// Mitsubishi GX Works2 project: 三菱模版   PLC: FX3U/FX3UC

PROGRAM MAIN
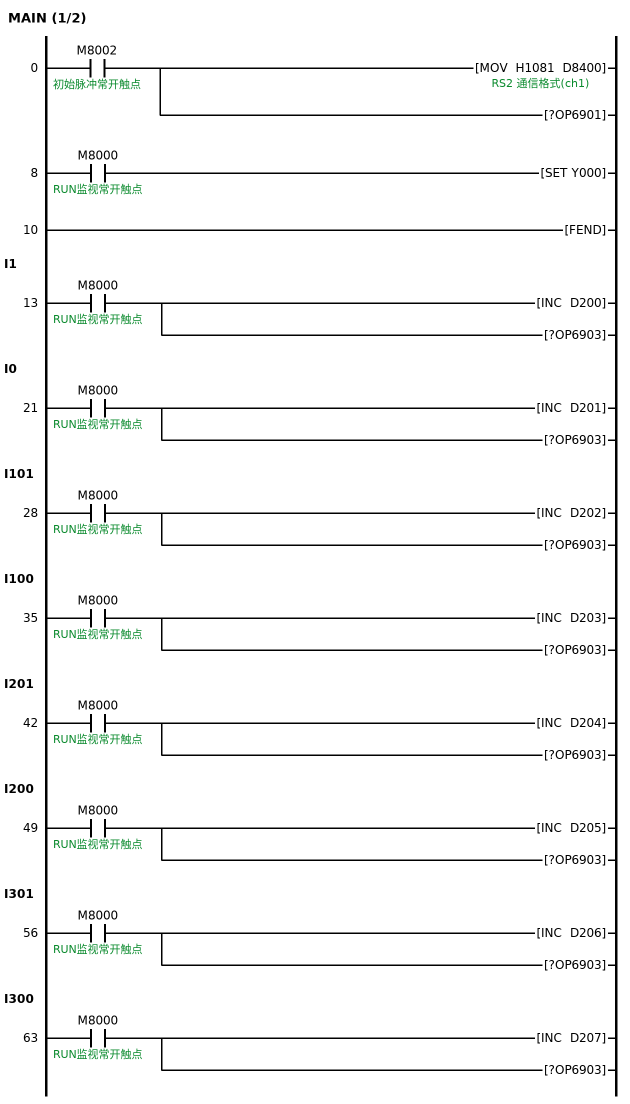
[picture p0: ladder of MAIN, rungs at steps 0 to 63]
0     LD      M8002  ; 初始脉冲常开触点
      MOV     H1081 D8400  ; RS2 通信格式(ch1)
      ?OP6901
        [note] 允许中断
8     LD      M8000  ; RUN监视常开触点
      SET     Y000
10    FEND
        [note] 主程序结束
      I1
13    LD      M8000  ; RUN监视常开触点
      INC     D200
        [note] X0上升沿中断
      ?OP6903
        [note] 中断返回
      I0
21    LD      M8000  ; RUN监视常开触点
      INC     D201
        [note] X0下降沿中断
      ?OP6903
      I101
28    LD      M8000  ; RUN监视常开触点
      INC     D202
        [note] X1上升沿中断
      ?OP6903
      I100
35    LD      M8000  ; RUN监视常开触点
      INC     D203
        [note] X1下降沿中断
      ?OP6903
      I201
42    LD      M8000  ; RUN监视常开触点
      INC     D204
        [note] X2上升沿中断
      ?OP6903
      I200
49    LD      M8000  ; RUN监视常开触点
      INC     D205
        [note] X2下降沿中断
      ?OP6903
      I301
56    LD      M8000  ; RUN监视常开触点
      INC     D206
        [note] X3上升沿中断
      ?OP6903
      I300
63    LD      M8000  ; RUN监视常开触点
      INC     D207
        [note] X3下降沿中断
      ?OP6903
      I401
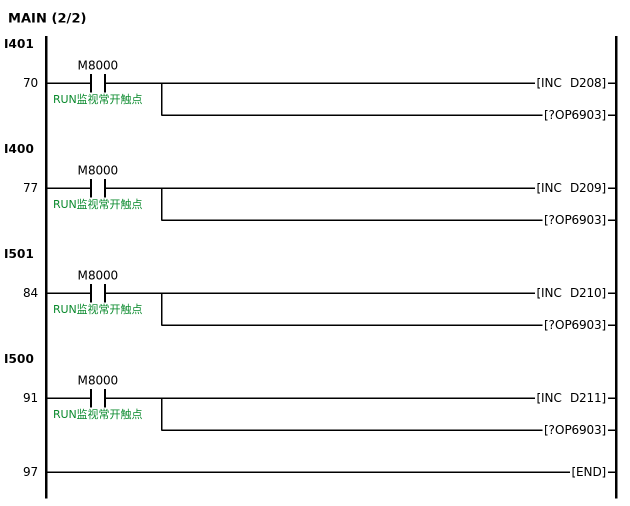
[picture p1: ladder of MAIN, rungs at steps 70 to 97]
70    LD      M8000  ; RUN监视常开触点
      INC     D208
        [note] x4上升沿中断
      ?OP6903
      I400
77    LD      M8000  ; RUN监视常开触点
      INC     D209
        [note] X4下降沿中断
      ?OP6903
      I501
84    LD      M8000  ; RUN监视常开触点
      INC     D210
        [note] X5上升沿中断
      ?OP6903
      I500
91    LD      M8000  ; RUN监视常开触点
      INC     D211
        [note] X5下降沿中断
      ?OP6903
97    END
END_PROGRAM

// device comments not shown above
C10  ; CCD1拍照连续不良计数
C11  ; CCD2连续不良计数
